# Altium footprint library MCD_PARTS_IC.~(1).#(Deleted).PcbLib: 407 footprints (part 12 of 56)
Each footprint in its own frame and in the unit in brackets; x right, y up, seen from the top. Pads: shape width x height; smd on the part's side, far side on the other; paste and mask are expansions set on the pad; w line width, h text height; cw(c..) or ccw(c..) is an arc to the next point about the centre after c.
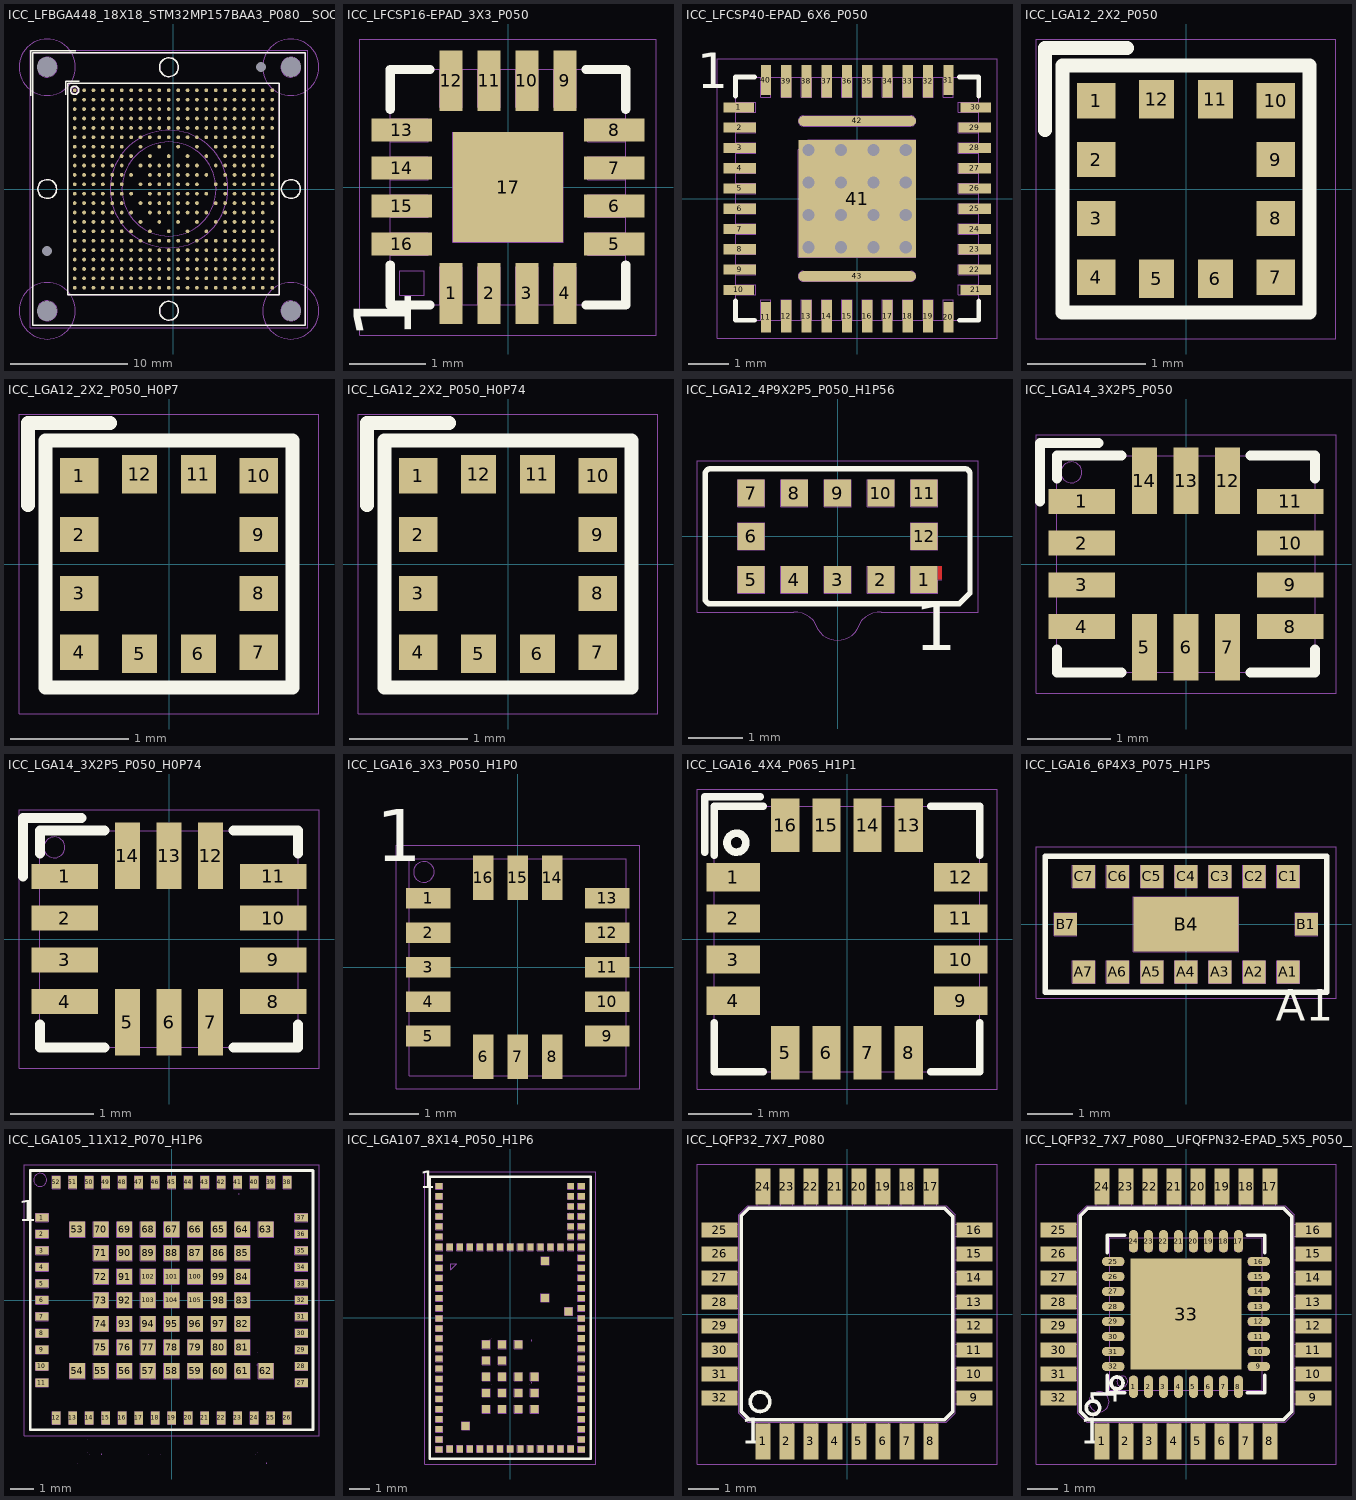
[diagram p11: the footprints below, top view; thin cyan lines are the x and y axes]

## ICC_LFBGA448_18X18_STM32MP157BAA3_P080__SOCKET_IE_CS1627194MF [mm]
height 10.2
pads (454):
  round 0.32 smd mask+0.05: A1(-8.4,8.4) A2(-7.6,8.4) A3(-6.8,8.4) A4(-6,8.4) A5(-5.2,8.4) A6(-4.4,8.4) A7(-3.6,8.4) A8(-2.8,8.4) A9(-2,8.4) A10(-1.2,8.4) A11(-0.4,8.4) A12(0.4,8.4) A13(1.2,8.4) A14(2,8.4) A15(2.8,8.4) A16(3.6,8.4) A17(4.4,8.4) A18(5.2,8.4) A19(6,8.4) A20(6.8,8.4) A21(7.6,8.4) A22(8.4,8.4) AA1(-8.4,-7.6) AA2(-7.6,-7.6) AA3(-6.8,-7.6) AA4(-6,-7.6) AA5(-5.2,-7.6) AA6(-4.4,-7.6) AA7(-3.6,-7.6) AA8(-2.8,-7.6) AA9(-2,-7.6) AA10(-1.2,-7.6) AA11(-0.4,-7.6) AA12(0.4,-7.6) AA13(1.2,-7.6) AA14(2,-7.6) AA15(2.8,-7.6) AA16(3.6,-7.6) AA17(4.4,-7.6) AA18(5.2,-7.6) AA19(6,-7.6) AA20(6.8,-7.6) AA21(7.6,-7.6) AA22(8.4,-7.6) AB1(-8.4,-8.4) AB2(-7.6,-8.4) AB3(-6.8,-8.4) AB4(-6,-8.4) AB5(-5.2,-8.4) AB6(-4.4,-8.4) AB7(-3.6,-8.4) AB8(-2.8,-8.4) AB9(-2,-8.4) AB10(-1.2,-8.4) AB11(-0.4,-8.4) AB12(0.4,-8.4) AB13(1.2,-8.4) AB14(2,-8.4) AB15(2.8,-8.4) AB16(3.6,-8.4) AB17(4.4,-8.4) AB18(5.2,-8.4) AB19(6,-8.4) AB20(6.8,-8.4) AB21(7.6,-8.4) AB22(8.4,-8.4) B1(-8.4,7.6) B2(-7.6,7.6) B3(-6.8,7.6) B4(-6,7.6) B5(-5.2,7.6) B6(-4.4,7.6) B7(-3.6,7.6) B8(-2.8,7.6) B9(-2,7.6) B10(-1.2,7.6) B11(-0.4,7.6) B12(0.4,7.6) B13(1.2,7.6) B14(2,7.6) B15(2.8,7.6) B16(3.6,7.6) B17(4.4,7.6) B18(5.2,7.6) B19(6,7.6) B20(6.8,7.6) B21(7.6,7.6) B22(8.4,7.6) C1(-8.4,6.8) C2(-7.6,6.8) C3(-6.8,6.8) C4(-6,6.8) C5(-5.2,6.8) C6(-4.4,6.8) C7(-3.6,6.8) C8(-2.8,6.8) C9(-2,6.8) C10(-1.2,6.8) C11(-0.4,6.8) C12(0.4,6.8) C13(1.2,6.8) C14(2,6.8) C15(2.8,6.8) C16(3.6,6.8) C17(4.4,6.8) C18(5.2,6.8) C19(6,6.8) C20(6.8,6.8) C21(7.6,6.8) C22(8.4,6.8) D1(-8.4,6) D2(-7.6,6) D3(-6.8,6) D4(-6,6) D5(-5.2,6) D6(-4.4,6) D7(-3.6,6) D8(-2.8,6) D9(-2,6) D10(-1.2,6) D11(-0.4,6) D12(0.4,6) D13(1.2,6) D14(2,6) D15(2.8,6) D16(3.6,6) D17(4.4,6) D18(5.2,6) D19(6,6) D20(6.8,6) D21(7.6,6) D22(8.4,6) E1(-8.4,5.2) E2(-7.6,5.2) E3(-6.8,5.2) E4(-6,5.2) E5(-5.2,5.2) E6(-4.4,5.2) E7(-3.6,5.2) E8(-2.8,5.2) E9(-2,5.2) E10(-1.2,5.2) E11(-0.4,5.2) E12(0.4,5.2) E13(1.2,5.2) E14(2,5.2) E15(2.8,5.2) E16(3.6,5.2) E17(4.4,5.2) E18(5.2,5.2) E19(6,5.2) E20(6.8,5.2) E21(7.6,5.2) E22(8.4,5.2) F1(-8.4,4.4) F2(-7.6,4.4) F3(-6.8,4.4) F4(-6,4.4) F5(-5.2,4.4) F6(-4.4,4.4) F7(-3.6,4.4) F8(-2.8,4.4) F9(-2,4.4) F10(-1.2,4.4) F11(-0.4,4.4) F12(0.4,4.4) F13(1.2,4.4) F14(2,4.4) F15(2.8,4.4) F16(3.6,4.4) F17(4.4,4.4) F18(5.2,4.4) F19(6,4.4) F20(6.8,4.4) F21(7.6,4.4) G1(-8.4,3.6) G2(-7.6,3.6) G3(-6.8,3.6) G4(-6,3.6) G5(-5.2,3.6) G6(-4.4,3.6) G8(-2.8,3.6) G10(-1.2,3.6) G12(0.4,3.6) G14(2,3.6) G16(3.6,3.6) G17(4.4,3.6) G18(5.2,3.6) G19(6,3.6) G20(6.8,3.6) G21(7.6,3.6) G22(8.4,3.6) H1(-8.4,2.8) H2(-7.6,2.8) H3(-6.8,2.8) H4(-6,2.8) H5(-5.2,2.8) H6(-4.4,2.8) H7(-3.6,2.8) H9(-2,2.8) H11(-0.4,2.8) H13(1.2,2.8) H15(2.8,2.8) H17(4.4,2.8) H18(5.2,2.8) H19(6,2.8) H20(6.8,2.8) H21(7.6,2.8) H22(8.4,2.8) J1(-8.4,2) J2(-7.6,2) J3(-6.8,2) J4(-6,2) J5(-5.2,2) J6(-4.4,2) J8(-2.8,2) J9(-2,2) J10(-1.2,2) J11(-0.4,2) J12(0.4,2) J13(1.2,2) J14(2,2) J16(3.6,2) J17(4.4,2) J18(5.2,2) J19(6,2) J20(6.8,2) J21(7.6,2) K1(-8.4,1.2) K2(-7.6,1.2) K3(-6.8,1.2) K4(-6,1.2) K5(-5.2,1.2) K6(-4.4,1.2) K7(-3.6,1.2) K9(-2,1.2) K10(-1.2,1.2) K11(-0.4,1.2) K12(0.4,1.2) K13(1.2,1.2) K14(2,1.2) K15(2.8,1.2) K17(4.4,1.2) K18(5.2,1.2) K19(6,1.2) K20(6.8,1.2) K21(7.6,1.2) K22(8.4,1.2) L1(-8.4,0.4) L2(-7.6,0.4) L3(-6.8,0.4) L4(-6,0.4) L5(-5.2,0.4) L6(-4.4,0.4) L8(-2.8,0.4) L9(-2,0.4) L10(-1.2,0.4) L11(-0.4,0.4) L12(0.4,0.4) L13(1.2,0.4) L14(2,0.4) L16(3.6,0.4) L17(4.4,0.4) L18(5.2,0.4) L19(6,0.4) L20(6.8,0.4) L21(7.6,0.4) L22(8.4,0.4) M1(-8.4,-0.4) M2(-7.6,-0.4) M3(-6.8,-0.4) M4(-6,-0.4) M5(-5.2,-0.4) M6(-4.4,-0.4) M7(-3.6,-0.4) M9(-2,-0.4) M10(-1.2,-0.4) M11(-0.4,-0.4) M12(0.4,-0.4) M13(1.2,-0.4) M14(2,-0.4) M15(2.8,-0.4) M17(4.4,-0.4) M18(5.2,-0.4) M19(6,-0.4) M20(6.8,-0.4) M21(7.6,-0.4) M22(8.4,-0.4) N1(-8.4,-1.2) N2(-7.6,-1.2) N3(-6.8,-1.2) N4(-6,-1.2) N5(-5.2,-1.2) N6(-4.4,-1.2) N8(-2.8,-1.2) N9(-2,-1.2) N10(-1.2,-1.2) N11(-0.4,-1.2) N12(0.4,-1.2) N13(1.2,-1.2) N14(2,-1.2) N16(3.6,-1.2) N17(4.4,-1.2) N18(5.2,-1.2) N19(6,-1.2) N20(6.8,-1.2) N21(7.6,-1.2) N22(8.4,-1.2) P1(-8.4,-2) P2(-7.6,-2) P3(-6.8,-2) P4(-6,-2) P5(-5.2,-2) P6(-4.4,-2) P7(-3.6,-2) P9(-2,-2) P10(-1.2,-2) P11(-0.4,-2) P12(0.4,-2) P13(1.2,-2) P14(2,-2) P15(2.8,-2) P17(4.4,-2) P18(5.2,-2) P19(6,-2) P20(6.8,-2) P21(7.6,-2) R1(-8.4,-2.8) R2(-7.6,-2.8) R3(-6.8,-2.8) R4(-6,-2.8) R5(-5.2,-2.8) R6(-4.4,-2.8) R8(-2.8,-2.8) R10(-1.2,-2.8) R12(0.4,-2.8) R14(2,-2.8) R16(3.6,-2.8) R17(4.4,-2.8) R18(5.2,-2.8) R19(6,-2.8) R20(6.8,-2.8) R21(7.6,-2.8) R22(8.4,-2.8) T1(-8.4,-3.6) T2(-7.6,-3.6) T3(-6.8,-3.6) T4(-6,-3.6) T5(-5.2,-3.6) T6(-4.4,-3.6) T7(-3.6,-3.6) T9(-2,-3.6) T11(-0.4,-3.6) T13(1.2,-3.6) T15(2.8,-3.6) T17(4.4,-3.6) T18(5.2,-3.6) T19(6,-3.6) T20(6.8,-3.6) T21(7.6,-3.6) T22(8.4,-3.6) U1(-8.4,-4.4) U2(-7.6,-4.4) U3(-6.8,-4.4) U4(-6,-4.4) U5(-5.2,-4.4) U6(-4.4,-4.4) U7(-3.6,-4.4) U8(-2.8,-4.4) U9(-2,-4.4) U10(-1.2,-4.4) U11(-0.4,-4.4) U12(0.4,-4.4) U13(1.2,-4.4) U14(2,-4.4) U15(2.8,-4.4) U16(3.6,-4.4) U17(4.4,-4.4) U18(5.2,-4.4) U19(6,-4.4) U20(6.8,-4.4) U21(7.6,-4.4) V1(-8.4,-5.2) V2(-7.6,-5.2) V3(-6.8,-5.2) V4(-6,-5.2) V5(-5.2,-5.2) V6(-4.4,-5.2) V7(-3.6,-5.2) V8(-2.8,-5.2) V9(-2,-5.2) V10(-1.2,-5.2) V11(-0.4,-5.2) V12(0.4,-5.2) V13(1.2,-5.2) V14(2,-5.2) V15(2.8,-5.2) V16(3.6,-5.2) V17(4.4,-5.2) V18(5.2,-5.2) V19(6,-5.2) V20(6.8,-5.2) V21(7.6,-5.2) V22(8.4,-5.2) W1(-8.4,-6) W2(-7.6,-6) W3(-6.8,-6) W4(-6,-6) W5(-5.2,-6) W6(-4.4,-6) W7(-3.6,-6) W8(-2.8,-6) W9(-2,-6) W10(-1.2,-6) W11(-0.4,-6) W12(0.4,-6) W13(1.2,-6) W14(2,-6) W15(2.8,-6) W16(3.6,-6) W17(4.4,-6) W18(5.2,-6) W19(6,-6) W20(6.8,-6) W21(7.6,-6) W22(8.4,-6) Y1(-8.4,-6.8) Y2(-7.6,-6.8) Y3(-6.8,-6.8) Y4(-6,-6.8) Y5(-5.2,-6.8) Y6(-4.4,-6.8) Y7(-3.6,-6.8) Y8(-2.8,-6.8) Y9(-2,-6.8) Y10(-1.2,-6.8) Y11(-0.4,-6.8) Y12(0.4,-6.8) Y13(1.2,-6.8) Y14(2,-6.8) Y15(2.8,-6.8) Y16(3.6,-6.8) Y17(4.4,-6.8) Y18(5.2,-6.8) Y19(6,-6.8) Y20(6.8,-6.8) Y21(7.6,-6.8) Y22(8.4,-6.8)
  round 0.5 hole 1.7 unplated mask+0.05: NPTH1(-10.737,10.362) NPTH2(9.987,10.362) NPTH3(-10.737,-10.362) NPTH4(9.987,-10.362)
  round 0.5 hole 0.85 unplated mask+0.05: NPTH5(-10.737,-5.282) NPTH6(7.447,10.362)
Top Overlay:
  circle w0.12: c-8.4,8.4 r0.35
  circle w0.12: c-0.375,10.362 r0.8
  circle w0.12: c-0.375,-10.362 r0.8
  circle w0.12: c9.987,0 r0.8
  circle w0.12: c-10.737,0 r0.8
  lines w0.12: -12.125,7.95 -12.125,11.75 -8.325,11.75 ; -9.15,8 -9.15,9.15 -8,9.15 ; -11.987,-11.613 -11.987,11.612 11.238,11.612 11.238,-11.613 -11.987,-11.613 ; -9,-9 -9,9 9,9 9,-9 -9,-9
Bottom Overlay:
  circle w0.12: c-10.737,-10.362 r2.4
  circle w0.12: c-10.737,10.362 r2.4
  circle w0.12: c9.987,10.362 r2.4
  circle w0.12: c9.987,-10.362 r2.4
  circle w0.12: c-10.737,-10.362 r1
  circle w0.12: c-10.737,10.362 r1
  circle w0.12: c9.987,10.362 r1
  circle w0.12: c9.987,-10.362 r1
M14-Top Assembly:
  circle w0.01: c-0.375,10.362 r0.8
  circle w0.01: c-0.375,-10.362 r0.8
  circle w0.01: c9.987,0 r0.8
  circle w0.01: c-10.737,0 r0.8
  circle w0.01: c-8.4,8.4 r0.275
  circle w0.01: c-0.375,0 r4
  circle w0.01: c-0.375,0 r5
  lines w0.01: -11.987,-11.613 -11.987,11.612 11.238,11.612 11.238,-11.613 -11.987,-11.613 ; -9,-9 -9,9 9,9 9,-9 -9,-9
  text "'.Designator'" at -2,-0.5 h0.75
  text "A1" at -8.65,8.225 h0.4
M15-Bottom Assembly:
  circle w0.01: c-10.737,-10.362 r2.4
  circle w0.01: c-10.737,10.362 r2.4
  circle w0.01: c9.987,10.362 r2.4
  circle w0.01: c9.987,-10.362 r2.4
  circle w0.01: c-10.737,-10.362 r0.85
  circle w0.01: c-10.737,10.362 r0.85
  circle w0.01: c9.987,10.362 r0.85
  circle w0.01: c9.987,-10.362 r0.85
M16-Top Courtyard:
  lines w0.01: -12.2,-11.825 -12.2,11.825 11.45,11.825 11.45,-11.825 -12.2,-11.825
3D body: height 7, standoff 0, extent -11.987,-11.613 11.238,11.612
3D body: height 9, standoff 7, extent -11.987,-11.613 11.238,11.612
3D body: height -1.6, standoff -5.42, extent 9.144,-11.21 10.837,-9.513
3D body: height -1.6, standoff -5.42, extent -11.58,-11.21 -9.887,-9.514
3D body: height -1.6, standoff -5.42, extent 9.144,9.514 10.837,11.211
3D body: height -1.6, standoff -5.42, extent -11.58,9.514 -9.887,11.21
3D body: height -1.6, standoff -2.87, extent 7.687,-12.662 12.287,-8.062
3D body: height -1.6, standoff -2.87, extent -13.037,-12.662 -8.437,-8.062
3D body: height -1.6, standoff -2.87, extent 7.687,8.062 12.287,12.662
3D body: height -1.6, standoff -2.87, extent -13.037,8.062 -8.437,12.662
3D body: height -1.6, standoff -2.23, extent 7.587,-12.762 12.387,-7.962
3D body: height -1.6, standoff -2.23, extent 7.587,7.962 12.387,12.762
3D body: height -1.6, standoff -2.23, extent -13.137,7.962 -8.337,12.762
3D body: height -1.6, standoff -2.23, extent -13.137,-12.762 -8.337,-7.962
3D body: height 9.87, standoff 9, extent -5.375,-5 4.625,5
3D body: height 9.87, standoff 9, extent -4.375,-3.997 3.625,3.997
3D body: height 10.18, standoff 9, extent -11.531,-0.798 -9.937,0.799
3D body: height 10.18, standoff 9, extent -1.169,9.564 0.425,11.161
3D body: height 10.18, standoff 9, extent 9.193,-0.798 10.787,0.799
3D body: height 10.18, standoff 9, extent -1.169,-11.16 0.425,-9.563

## ICC_LFCSP16-EPAD_3X3_P050 [mm] "MCD-02980"
height 0.8
pads (17):
  rect 0.3x0.8 smd mask+0.05: 1(-0.75,-1.4) 2(-0.25,-1.4) 3(0.25,-1.4) 4(0.75,-1.4) 9(0.75,1.4) 10(0.25,1.4) 11(-0.25,1.4) 12(-0.75,1.4)
  rect 0.8x0.3 smd mask+0.05: 5(1.4,-0.75) 6(1.4,-0.25) 7(1.4,0.25) 8(1.4,0.75) 13(-1.4,0.75) 14(-1.4,0.25) 15(-1.4,-0.25) 16(-1.4,-0.75)
  rect 1.45x1.45 smd mask+0.05: 17(0,0)
Top Overlay:
  lines w0.12: -1.55,-1.025 -1.55,-1.55 -1.025,-1.55 ; -1.55,1.025 -1.55,1.55 -1.025,1.55 ; 1.025,-1.55 1.55,-1.55 1.55,-1.025 ; 1.025,1.55 1.55,1.55 1.55,1.025
  text "1" at -1.025,-2 h1.3
M14-Top Assembly:
  lines w0.01: -1.55,-0.9 -1.05,-0.9 -1.05,-0.6 -1.55,-0.6 ; -1.55,-0.4 -1.05,-0.4 -1.05,-0.1 -1.55,-0.1 ; -1.55,0.1 -1.05,0.1 -1.05,0.4 -1.55,0.4 ; -1.55,0.6 -1.05,0.6 -1.05,0.9 -1.55,0.9 ; -0.9,-1.55 -0.9,-1.05 -0.6,-1.05 -0.6,-1.55 ; -0.9,1.55 -0.9,1.05 -0.6,1.05 -0.6,1.55 ; -0.4,-1.55 -0.4,-1.05 -0.1,-1.05 -0.1,-1.55 ; -0.4,1.55 -0.4,1.05 -0.1,1.05 -0.1,1.55 ; 0.1,-1.55 0.1,-1.05 0.4,-1.05 0.4,-1.55 ; 0.1,1.55 0.1,1.05 0.4,1.05 0.4,1.55 ; 0.6,-1.55 0.6,-1.05 0.9,-1.05 0.9,-1.55 ; 0.6,1.55 0.6,1.05 0.9,1.05 0.9,1.55 ; 1.55,-0.9 1.05,-0.9 1.05,-0.6 1.55,-0.6 ; 1.55,-0.4 1.05,-0.4 1.05,-0.1 1.55,-0.1 ; 1.55,0.1 1.05,0.1 1.05,0.4 1.55,0.4 ; 1.55,0.6 1.05,0.6 1.05,0.9 1.55,0.9 ; -1.55,-1.55 1.55,-1.55 1.55,1.55 -1.55,1.55 -1.55,-1.55 ; -1.425,-1.425 -1.1,-1.425 -1.1,-1.1 -1.425,-1.1 -1.425,-1.425 ; -0.725,-0.725 0.725,-0.725 0.725,0.725 -0.725,0.725 -0.725,-0.725
  text "16" at -1.4,-0.575 h0.4
  text "13" at -1.4,0.925 h0.4
  text "12" at -0.575,1.4 h0.4
  text "9" at 0.805,1.399 h0.4
  text "8" at 1.399,0.66 h0.4
  text "5" at 1.399,-0.805 h0.4
  text "'.Designator'" at -2,-0.5 h0.75
  text "17" at -0.15,-0.125 h0.4
  text "4" at 0.66,-1.399 h0.4
  text "1" at -0.805,-1.399 h0.4
M16-Top Courtyard:
  lines w0.01: -1.95,-1.95 -1.95,1.95 1.95,1.95 1.95,-1.95 -1.95,-1.95
3D body: height 0.8, standoff 0, extent -1.55,-1.55 1.55,1.55

## ICC_LFCSP40-EPAD_6X6_P050 [mm] "MCD-02639"
height 0.8
pads (43):
  rect 0.75x0.25 smd mask+0.05: 1(-2.925,2.25) 10(-2.925,-2.25) 21(2.925,-2.25) 30(2.925,2.25)
  rect 0.8x0.25 smd mask+0.05: 2(-2.9,1.75) 3(-2.9,1.25) 4(-2.9,0.75) 5(-2.9,0.25) 6(-2.9,-0.25) 7(-2.9,-0.75) 8(-2.9,-1.25) 9(-2.9,-1.75) 22(2.9,-1.75) 23(2.9,-1.25) 24(2.9,-0.75) 25(2.9,-0.25) 26(2.9,0.25) 27(2.9,0.75) 28(2.9,1.25) 29(2.9,1.75)
  rect 0.25x0.75 smd mask+0.05: 11(-2.25,-2.925) 20(2.25,-2.925) 31(2.25,2.925) 40(-2.25,2.925)
  rect 0.25x0.8 smd mask+0.05: 12(-1.75,-2.9) 13(-1.25,-2.9) 14(-0.75,-2.9) 15(-0.25,-2.9) 16(0.25,-2.9) 17(0.75,-2.9) 18(1.25,-2.9) 19(1.75,-2.9) 32(1.75,2.9) 33(1.25,2.9) 34(0.75,2.9) 35(0.25,2.9) 36(-0.25,2.9) 37(-0.75,2.9) 38(-1.25,2.9) 39(-1.75,2.9)
  rect 2.9x2.9 smd mask+0.05: 41(0,0)
  rrect100% 2.9x0.25 smd mask+0.05: 42(0,1.915) 43(0,-1.915)
via 1.2,-1.2 diameter 0.5 hole 0.3
via 0.4,-1.2 diameter 0.5 hole 0.3
via 0.4,-0.4 diameter 0.5 hole 0.3
via 1.2,-0.4 diameter 0.5 hole 0.3
via 1.2,0.4 diameter 0.5 hole 0.3
via 0.4,0.4 diameter 0.5 hole 0.3
via 1.2,1.2 diameter 0.5 hole 0.3
via 0.4,1.2 diameter 0.5 hole 0.3
via -0.4,1.2 diameter 0.5 hole 0.3
via -0.4,0.4 diameter 0.5 hole 0.3
via -0.4,-0.4 diameter 0.5 hole 0.3
via -0.4,-1.2 diameter 0.5 hole 0.3
via -1.2,-1.2 diameter 0.5 hole 0.3
via -1.2,-0.4 diameter 0.5 hole 0.3
via -1.2,0.4 diameter 0.5 hole 0.3
via -1.2,1.2 diameter 0.5 hole 0.3
Top Overlay:
  lines w0.12: -3,-2.525 -3,-3 -2.525,-3 ; -3,2.525 -3,3 -2.525,3 ; 2.525,-3 3,-3 3,-2.525 ; 2.525,3 3,3 3,2.525
  text "1" at -3.95,2.425 h1.5
M14-Top Assembly:
  lines w0.01: -3,-2.375 -2.5,-2.375 -2.5,-2.125 -3,-2.125 ; -3,-1.875 -2.5,-1.875 -2.5,-1.625 -3,-1.625 ; -3,-1.375 -2.5,-1.375 -2.5,-1.125 -3,-1.125 ; -3,-0.875 -2.5,-0.875 -2.5,-0.625 -3,-0.625 ; -3,-0.375 -2.5,-0.375 -2.5,-0.125 -3,-0.125 ; -3,0.125 -2.5,0.125 -2.5,0.375 -3,0.375 ; -3,0.625 -2.5,0.625 -2.5,0.875 -3,0.875 ; -3,1.125 -2.5,1.125 -2.5,1.375 -3,1.375 ; -3,1.625 -2.5,1.625 -2.5,1.875 -3,1.875 ; -3,2.125 -2.5,2.125 -2.5,2.375 -3,2.375 ; -2.375,-3 -2.375,-2.5 -2.125,-2.5 -2.125,-3 ; -2.375,3 -2.375,2.5 -2.125,2.5 -2.125,3 ; -1.875,-3 -1.875,-2.5 -1.625,-2.5 -1.625,-3 ; -1.875,3 -1.875,2.5 -1.625,2.5 -1.625,3 ; -1.375,-3 -1.375,-2.5 -1.125,-2.5 -1.125,-3 ; -1.375,3 -1.375,2.5 -1.125,2.5 -1.125,3 ; -0.875,-3 -0.875,-2.5 -0.625,-2.5 -0.625,-3 ; -0.875,3 -0.875,2.5 -0.625,2.5 -0.625,3 ; -0.375,-3 -0.375,-2.5 -0.125,-2.5 -0.125,-3 ; -0.375,3 -0.375,2.5 -0.125,2.5 -0.125,3 ; 0.125,-3 0.125,-2.5 0.375,-2.5 0.375,-3 ; 0.125,3 0.125,2.5 0.375,2.5 0.375,3 ; 0.625,-3 0.625,-2.5 0.875,-2.5 0.875,-3 ; 0.625,3 0.625,2.5 0.875,2.5 0.875,3 ; 1.125,-3 1.125,-2.5 1.375,-2.5 1.375,-3 ; 1.125,3 1.125,2.5 1.375,2.5 1.375,3 ; 1.625,-3 1.625,-2.5 1.875,-2.5 1.875,-3 ; 1.625,3 1.625,2.5 1.875,2.5 1.875,3 ; 2.125,-3 2.125,-2.5 2.375,-2.5 2.375,-3 ; 2.125,3 2.125,2.5 2.375,2.5 2.375,3 ; 3,-2.375 2.5,-2.375 2.5,-2.125 3,-2.125 ; 3,-1.875 2.5,-1.875 2.5,-1.625 3,-1.625 ; 3,-1.375 2.5,-1.375 2.5,-1.125 3,-1.125 ; 3,-0.875 2.5,-0.875 2.5,-0.625 3,-0.625 ; 3,-0.375 2.5,-0.375 2.5,-0.125 3,-0.125 ; 3,0.125 2.5,0.125 2.5,0.375 3,0.375 ; 3,0.625 2.5,0.625 2.5,0.875 3,0.875 ; 3,1.125 2.5,1.125 2.5,1.375 3,1.375 ; 3,1.625 2.5,1.625 2.5,1.875 3,1.875 ; 3,2.125 2.5,2.125 2.5,2.375 3,2.375 ; -3,-3 3,-3 3,3 -3,3 -3,-3 ; -1.45,-1.915 ccw(c-1.325,-1.915) -1.325,-2.04 1.325,-2.04 ccw(c1.325,-1.915) 1.45,-1.915 ccw(c1.325,-1.915) 1.325,-1.79 -1.325,-1.79 ccw(c-1.325,-1.915) -1.45,-1.915 ; -1.45,-1.45 1.45,-1.45 1.45,1.45 -1.2,1.45 -1.45,1.2 -1.45,-1.45 ; -1.45,1.915 cw(c-1.325,1.915) -1.325,2.04 1.325,2.04 cw(c1.325,1.915) 1.45,1.915 cw(c1.325,1.915) 1.325,1.79 -1.325,1.79 cw(c-1.325,1.915) -1.45,1.915
  text "40" at -2.475,2.575 h0.5
  text "31" at 2.075,2.6 h0.5
  text "30" at 2.5,2.1 h0.5
  text "21" at 2.5,-2.4 h0.5
  text "20" at 2,-2.9 h0.5
  text "11" at -2.475,-2.9 h0.5
  text "10" at -2.95,-2.4 h0.5
  text "1" at -2.85,2.1 h0.5
  text "'.Designator'" at 0,0 h0.75
M16-Top Courtyard:
  lines w0.01: -3.45,-3.45 3.45,-3.45 3.45,3.45 -1.45,3.45 -3.45,3.45 -3.45,-3.45
3D body: height 0.82, standoff 0.81, extent -2.848,2.351 -2.35,2.85
3D body: height 0.61, standoff 0.6, extent -2.848,2.351 -2.35,2.85
3D body: height 0.8, standoff 0, extent -3,-3 3,3

## ICC_LGA12_2X2_P050 [mm] "MCD-00709"
height 1
pads (12):
  rect 0.325x0.3 smd mask+0.05: 1(-0.763,0.75) 2(-0.763,0.25) 3(-0.763,-0.25) 4(-0.763,-0.75) 7(0.763,-0.75) 8(0.763,-0.25) 9(0.763,0.25) 10(0.763,0.75)
  rect 0.3x0.325 smd mask+0.05: 5(-0.25,-0.762) 6(0.25,-0.762) 11(0.25,0.763) 12(-0.25,0.763)
Top Overlay:
  lines w0.12: -1.2,0.5 -1.2,1.2 -0.5,1.2 ; -1.05,-1.05 -1.05,1.05 1.05,1.05 1.05,-1.05 -1.05,-1.05
M14-Top Assembly:
  lines w0.01: -1.05,-1.05 1.05,-1.05 1.05,1.05 -1.05,1.05 -1.05,-1.05 ; -0.9,-0.875 -0.625,-0.875 -0.625,-0.625 -0.9,-0.625 -0.9,-0.875 ; -0.9,-0.375 -0.625,-0.375 -0.625,-0.125 -0.9,-0.125 -0.9,-0.375 ; -0.9,0.125 -0.625,0.125 -0.625,0.375 -0.9,0.375 -0.9,0.125 ; -0.9,0.625 -0.75,0.625 -0.625,0.75 -0.625,0.875 -0.9,0.875 -0.9,0.625 ; -0.375,-0.9 -0.125,-0.9 -0.125,-0.625 -0.375,-0.625 -0.375,-0.9 ; -0.375,0.625 -0.375,0.9 -0.125,0.9 -0.125,0.625 -0.375,0.625 ; 0.125,-0.9 0.375,-0.9 0.375,-0.625 0.125,-0.625 0.125,-0.9 ; 0.125,0.625 0.375,0.625 0.375,0.9 0.125,0.9 0.125,0.625 ; 0.625,-0.875 0.9,-0.875 0.9,-0.625 0.625,-0.625 0.625,-0.875 ; 0.625,-0.375 0.9,-0.375 0.9,-0.125 0.625,-0.125 0.625,-0.375 ; 0.625,0.125 0.9,0.125 0.9,0.375 0.625,0.375 0.625,0.125 ; 0.625,0.625 0.9,0.625 0.9,0.875 0.625,0.875 0.625,0.625
  text "'.Designator'" at -2,-0.5 h0.75
  text "1" at -0.825,0.65 h0.3
  text "2" at -0.825,0.15 h0.3
  text "3" at -0.825,-0.35 h0.3
  text "4" at -0.825,-0.85 h0.3
  text "5" at -0.325,-0.85 h0.3
  text "6" at 0.175,-0.85 h0.3
  text "7" at 0.7,-0.85 h0.3
  text "8" at 0.7,-0.35 h0.3
  text "9" at 0.7,0.15 h0.3
  text "10" at 0.637,0.65 h0.3
  text "12" at -0.375,0.663 h0.3
  text "11" at 0.138,0.663 h0.3
M16-Top Courtyard:
  lines w0.01: -1.275,-1.275 1.275,-1.275 1.275,1.275 -1.275,1.275 -1.275,-1.275
3D body: height 1.01, standoff 1, extent -0.998,0.501 -0.5,1
3D body: height 1, standoff 0, extent -1.05,-1.05 1.05,1.05
3D body "LGA12-2x2x0_9.STEP": height 0.95, standoff 0, extent -1,-1 1,1

## ICC_LGA12_2X2_P050_H0P7 [mm] "MCD-01448"
height 0.7
pads (12):
  rect 0.325x0.3 smd mask+0.05: 1(-0.763,0.75) 2(-0.763,0.25) 3(-0.763,-0.25) 4(-0.763,-0.75) 7(0.763,-0.75) 8(0.763,-0.25) 9(0.763,0.25) 10(0.763,0.75)
  rect 0.3x0.325 smd mask+0.05: 5(-0.25,-0.762) 6(0.25,-0.762) 11(0.25,0.763) 12(-0.25,0.763)
Top Overlay:
  lines w0.12: -1.2,0.5 -1.2,1.2 -0.5,1.2 ; -1.05,-1.05 1.05,-1.05 1.05,1.05 -1.05,1.05 -1.05,-1.05
M14-Top Assembly:
  lines w0.01: -1.05,-1.05 -1.05,1.05 1.05,1.05 1.05,-1.05 -1.05,-1.05 ; -0.9,-0.875 -0.9,-0.625 -0.625,-0.625 -0.625,-0.875 -0.9,-0.875 ; -0.9,-0.375 -0.9,-0.125 -0.625,-0.125 -0.625,-0.375 -0.9,-0.375 ; -0.9,0.125 -0.9,0.375 -0.625,0.375 -0.625,0.125 -0.9,0.125 ; -0.9,0.625 -0.9,0.875 -0.625,0.875 -0.625,0.75 -0.75,0.625 -0.9,0.625 ; -0.375,-0.9 -0.375,-0.625 -0.125,-0.625 -0.125,-0.9 -0.375,-0.9 ; -0.375,0.625 -0.125,0.625 -0.125,0.9 -0.375,0.9 -0.375,0.625 ; 0.125,-0.9 0.125,-0.625 0.375,-0.625 0.375,-0.9 0.125,-0.9 ; 0.125,0.625 0.125,0.9 0.375,0.9 0.375,0.625 0.125,0.625 ; 0.625,-0.875 0.625,-0.625 0.9,-0.625 0.9,-0.875 0.625,-0.875 ; 0.625,-0.375 0.625,-0.125 0.9,-0.125 0.9,-0.375 0.625,-0.375 ; 0.625,0.125 0.625,0.375 0.9,0.375 0.9,0.125 0.625,0.125 ; 0.625,0.625 0.625,0.875 0.9,0.875 0.9,0.625 0.625,0.625
  text "11" at 0.138,0.663 h0.3
  text "12" at -0.375,0.663 h0.3
  text "10" at 0.637,0.65 h0.3
  text "9" at 0.7,0.15 h0.3
  text "8" at 0.7,-0.35 h0.3
  text "7" at 0.7,-0.85 h0.3
  text "6" at 0.175,-0.85 h0.3
  text "5" at -0.325,-0.85 h0.3
  text "4" at -0.825,-0.85 h0.3
  text "3" at -0.825,-0.35 h0.3
  text "2" at -0.825,0.15 h0.3
  text "1" at -0.825,0.65 h0.3
  text "'.Designator'" at -2,-0.5 h0.75
M16-Top Courtyard:
  lines w0.01: -1.275,-1.275 -1.275,1.275 1.275,1.275 1.275,-1.275 -1.275,-1.275
3D body: height 0.7, standoff 0, extent -1.05,-1.05 1.05,1.05
3D body: height 0.71, standoff 0.7, extent -0.998,0.501 -0.5,1

## ICC_LGA12_2X2_P050_H0P74 [mm]
height 0.74
pads (12):
  rect 0.325x0.3 smd mask+0.05: 1(-0.763,0.75) 2(-0.763,0.25) 3(-0.763,-0.25) 4(-0.763,-0.75) 7(0.763,-0.75) 8(0.763,-0.25) 9(0.763,0.25) 10(0.763,0.75)
  rect 0.3x0.325 smd mask+0.05: 5(-0.25,-0.762) 6(0.25,-0.762) 11(0.25,0.763) 12(-0.25,0.763)
Top Overlay:
  lines w0.12: -1.2,0.5 -1.2,1.2 -0.5,1.2 ; -1.05,-1.05 -1.05,1.05 1.05,1.05 1.05,-1.05 -1.05,-1.05
M14-Top Assembly:
  lines w0.01: -1.05,-1.05 1.05,-1.05 1.05,1.05 -1.05,1.05 -1.05,-1.05 ; -0.9,-0.875 -0.625,-0.875 -0.625,-0.625 -0.9,-0.625 -0.9,-0.875 ; -0.9,-0.375 -0.625,-0.375 -0.625,-0.125 -0.9,-0.125 -0.9,-0.375 ; -0.9,0.125 -0.625,0.125 -0.625,0.375 -0.9,0.375 -0.9,0.125 ; -0.9,0.625 -0.75,0.625 -0.625,0.75 -0.625,0.875 -0.9,0.875 -0.9,0.625 ; -0.375,-0.9 -0.125,-0.9 -0.125,-0.625 -0.375,-0.625 -0.375,-0.9 ; -0.375,0.625 -0.375,0.9 -0.125,0.9 -0.125,0.625 -0.375,0.625 ; 0.125,-0.9 0.375,-0.9 0.375,-0.625 0.125,-0.625 0.125,-0.9 ; 0.125,0.625 0.375,0.625 0.375,0.9 0.125,0.9 0.125,0.625 ; 0.625,-0.875 0.9,-0.875 0.9,-0.625 0.625,-0.625 0.625,-0.875 ; 0.625,-0.375 0.9,-0.375 0.9,-0.125 0.625,-0.125 0.625,-0.375 ; 0.625,0.125 0.9,0.125 0.9,0.375 0.625,0.375 0.625,0.125 ; 0.625,0.625 0.9,0.625 0.9,0.875 0.625,0.875 0.625,0.625
  text "'.Designator'" at -2,-0.5 h0.75
  text "1" at -0.825,0.65 h0.3
  text "2" at -0.825,0.15 h0.3
  text "3" at -0.825,-0.35 h0.3
  text "4" at -0.825,-0.85 h0.3
  text "5" at -0.325,-0.85 h0.3
  text "6" at 0.175,-0.85 h0.3
  text "7" at 0.7,-0.85 h0.3
  text "8" at 0.7,-0.35 h0.3
  text "9" at 0.7,0.15 h0.3
  text "10" at 0.637,0.65 h0.3
  text "12" at -0.375,0.663 h0.3
  text "11" at 0.138,0.663 h0.3
M16-Top Courtyard:
  lines w0.01: -1.275,-1.275 1.275,-1.275 1.275,1.275 -1.275,1.275 -1.275,-1.275
3D body: height 0.75, standoff 0.74, extent -0.95,0.55 -0.55,0.95
3D body: height 0.74, standoff 0, extent -1.05,-1.05 1.05,1.05

## ICC_LGA12_4P9X2P5_P050_H1P56 [mm] "MCD-02083"
height 1.56
pads (12):
  rect 0.5x0.5 smd mask+0.05: 1(1.6,-0.8) 2(0.8,-0.8) 3(0,-0.8) 4(-0.8,-0.8) 5(-1.6,-0.8) 6(-1.6,0) 7(-1.6,0.8) 8(-0.8,0.8) 9(0,0.8) 10(0.8,0.8) 11(1.6,0.8) 12(1.6,0)
Top Layer:
  rectangle: 1.85,-0.8 1.93,-0.55
Top Overlay:
  lines w0.1: -2.45,-1.15 ccw(c-2.35,-1.15) -2.35,-1.25 2.25,-1.25 2.45,-1.05 2.45,1.15 ccw(c2.35,1.15) 2.35,1.25 -2.35,1.25 ccw(c-2.35,1.15) -2.45,1.15 -2.45,-1.15
  text "1" at 1.425,-2.4 h1.52
M14-Top Assembly:
  lines w0.01: -2.45,-1.15 ccw(c-2.35,-1.15) -2.35,-1.25 2.25,-1.25 2.45,-1.05 2.45,1.15 ccw(c2.35,1.15) 2.35,1.25 -2.35,1.25 ccw(c-2.35,1.15) -2.45,1.15 -2.45,-1.15 ; -1.85,-1.05 -1.85,-0.55 -1.35,-0.55 -1.35,-1.05 -1.85,-1.05 ; -1.85,-0.25 -1.85,0.25 -1.35,0.25 -1.35,-0.25 -1.85,-0.25 ; -1.85,0.55 -1.85,1.05 -1.35,1.05 -1.35,0.55 -1.85,0.55 ; -1.05,-1.05 -1.05,-0.55 -0.55,-0.55 -0.55,-1.05 -1.05,-1.05 ; -1.05,0.55 -1.05,1.05 -0.55,1.05 -0.55,0.55 -1.05,0.55 ; -0.25,-1.05 -0.25,-0.55 0.25,-0.55 0.25,-1.05 -0.25,-1.05 ; -0.25,0.55 -0.25,1.05 0.25,1.05 0.25,0.55 -0.25,0.55 ; 0.55,-1.05 1.05,-1.05 1.05,-0.55 0.55,-0.55 0.55,-1.05 ; 0.55,0.55 0.55,1.05 1.05,1.05 1.05,0.55 0.55,0.55 ; 1.35,-1.05 1.35,-0.55 1.93,-0.55 1.93,-0.8 1.85,-0.8 1.85,-1.05 1.35,-1.05 ; 1.35,-0.25 1.35,0.25 1.85,0.25 1.85,-0.25 1.35,-0.25 ; 1.35,0.55 1.35,1.05 1.85,1.05 1.85,0.55 1.35,0.55
  text "'.Designator'" at -2,-0.5 h0.75
  text "1" at 1.525,-0.95 h0.5
  text "2" at 0.7,-0.95 h0.5
  text "3" at -0.1,-0.95 h0.5
  text "4" at -0.925,-0.95 h0.5
  text "5" at -1.7,-0.95 h0.5
  text "6" at -1.7,-0.15 h0.5
  text "7" at -1.7,0.65 h0.5
  text "8" at -0.9,0.65 h0.5
  text "9" at -0.1,0.65 h0.5
  text "10" at 0.575,0.65 h0.5
  text "11" at 1.4,0.65 h0.5
  text "12" at 1.4,-0.15 h0.5
M16-Top Courtyard:
  lines w0.01: -2.6,-1.4 -0.812,-1.4 cw(c-0.812,-1.912) -0.45,-1.55 -0.4,-1.654 ccw(c0,-1.485) 0,-1.92 ccw(c0,-1.485) 0.4,-1.654 0.45,-1.55 cw(c0.812,-1.912) 0.812,-1.4 2.6,-1.4 2.6,1.4 -2.6,1.4 -2.6,-1.4
3D body: height 1.56, standoff 0, extent -2.45,-1.25 2.45,1.25
3D body "User Library-vl53l1x.STEP": height 1.58, standoff -0.01, extent -2.45,-1.25 2.45,1.25

## ICC_LGA14_3X2P5_P050 [mm] "MCD-01387"
height 0.86
pads (14):
  rect 0.8x0.3 smd mask+0.05: 1(-1.25,0.75) 2(-1.25,0.25) 3(-1.25,-0.25) 4(-1.25,-0.75) 8(1.25,-0.75) 9(1.25,-0.25) 10(1.25,0.25) 11(1.25,0.75)
  rect 0.3x0.8 smd mask+0.05: 5(-0.5,-1) 6(0,-1) 7(0.5,-1) 12(0.5,1) 13(0,1) 14(-0.5,1)
Top Overlay:
  lines w0.12: -1.75,0.75 -1.75,1.45 -1.05,1.45 ; -1.55,-1.025 -1.55,-1.3 -0.775,-1.3 ; -1.55,1.025 -1.55,1.3 -0.775,1.3 ; 0.775,-1.3 1.55,-1.3 1.55,-1.025 ; 0.775,1.3 1.55,1.3 1.55,1.025
M14-Top Assembly:
  circle w0.01: c-1.375,1.1 r0.125
  lines w0.01: -1.55,-1.3 -1.55,1.3 1.55,1.3 1.55,-1.3 -1.55,-1.3 ; -1.45,-0.875 -1.45,-0.625 -0.975,-0.625 -0.975,-0.875 -1.45,-0.875 ; -1.45,-0.375 -1.45,-0.125 -0.975,-0.125 -0.975,-0.375 -1.45,-0.375 ; -1.45,0.125 -1.45,0.375 -0.975,0.375 -0.975,0.125 -1.45,0.125 ; -1.45,0.625 -1.45,0.875 -0.975,0.875 -0.975,0.625 -1.45,0.625 ; -0.625,-1.2 -0.375,-1.2 -0.375,-0.725 -0.625,-0.725 -0.625,-1.2 ; -0.625,0.725 -0.625,1.2 -0.375,1.2 -0.375,0.725 -0.625,0.725 ; -0.125,-1.2 0.125,-1.2 0.125,-0.725 -0.125,-0.725 -0.125,-1.2 ; -0.125,0.725 -0.125,1.2 0.125,1.2 0.125,0.725 -0.125,0.725 ; 0.375,-1.2 0.625,-1.2 0.625,-0.725 0.375,-0.725 0.375,-1.2 ; 0.375,0.725 0.375,1.2 0.625,1.2 0.625,0.725 0.375,0.725 ; 0.975,-0.875 0.975,-0.625 1.45,-0.625 1.45,-0.875 0.975,-0.875 ; 0.975,-0.375 0.975,-0.125 1.45,-0.125 1.45,-0.375 0.975,-0.375 ; 0.975,0.125 0.975,0.375 1.45,0.375 1.45,0.125 0.975,0.125 ; 0.975,0.625 0.975,0.875 1.45,0.875 1.45,0.625 0.975,0.625
  text "14" at -0.7,0.8 h0.5
  text "12" at 0.275,0.8 h0.5
  text "8" at 1.375,-0.85 h0.5
  text "11" at 1.375,0.575 h0.5
  text "5" at -0.6,-1.125 h0.5
  text "7" at 0.4,-1.125 h0.5
  text "4" at -1.375,-0.64 h0.5
  text "1" at -1.375,0.825 h0.5
  text "'.Designator'" at -2,-0.5 h0.75
M16-Top Courtyard:
  lines w0.01: -1.8,-1.55 -1.8,1.55 -0.625,1.55 1.8,1.55 1.8,-1.55 -1.8,-1.55
3D body "LGA-14 2_5x3-1.STEP": height 0.86, standoff 0, extent -1.5,-1.25 1.5,1.25
3D body: height 0.86, standoff 0, extent -1.55,-1.3 1.55,1.3

## ICC_LGA14_3X2P5_P050_H0P74 [mm] "MCD-04163"
height 0.74
pads (14):
  rect 0.8x0.3 smd mask+0.05: 1(-1.25,0.75) 2(-1.25,0.25) 3(-1.25,-0.25) 4(-1.25,-0.75) 8(1.25,-0.75) 9(1.25,-0.25) 10(1.25,0.25) 11(1.25,0.75)
  rect 0.3x0.8 smd mask+0.05: 5(-0.5,-1) 6(0,-1) 7(0.5,-1) 12(0.5,1) 13(0,1) 14(-0.5,1)
Top Overlay:
  lines w0.12: -1.75,0.75 -1.75,1.45 -1.05,1.45 ; -1.55,-1.025 -1.55,-1.3 -0.775,-1.3 ; -1.55,1.025 -1.55,1.3 -0.775,1.3 ; 0.775,-1.3 1.55,-1.3 1.55,-1.025 ; 0.775,1.3 1.55,1.3 1.55,1.025
M14-Top Assembly:
  circle w0.01: c-1.375,1.1 r0.125
  lines w0.01: -1.55,-1.3 -1.55,1.3 1.55,1.3 1.55,-1.3 -1.55,-1.3 ; -1.45,-0.875 -1.45,-0.625 -0.975,-0.625 -0.975,-0.875 -1.45,-0.875 ; -1.45,-0.375 -1.45,-0.125 -0.975,-0.125 -0.975,-0.375 -1.45,-0.375 ; -1.45,0.125 -1.45,0.375 -0.975,0.375 -0.975,0.125 -1.45,0.125 ; -1.45,0.625 -1.45,0.875 -0.975,0.875 -0.975,0.625 -1.45,0.625 ; -0.625,-1.2 -0.375,-1.2 -0.375,-0.725 -0.625,-0.725 -0.625,-1.2 ; -0.625,0.725 -0.625,1.2 -0.375,1.2 -0.375,0.725 -0.625,0.725 ; -0.125,-1.2 0.125,-1.2 0.125,-0.725 -0.125,-0.725 -0.125,-1.2 ; -0.125,0.725 -0.125,1.2 0.125,1.2 0.125,0.725 -0.125,0.725 ; 0.375,-1.2 0.625,-1.2 0.625,-0.725 0.375,-0.725 0.375,-1.2 ; 0.375,0.725 0.375,1.2 0.625,1.2 0.625,0.725 0.375,0.725 ; 0.975,-0.875 0.975,-0.625 1.45,-0.625 1.45,-0.875 0.975,-0.875 ; 0.975,-0.375 0.975,-0.125 1.45,-0.125 1.45,-0.375 0.975,-0.375 ; 0.975,0.125 0.975,0.375 1.45,0.375 1.45,0.125 0.975,0.125 ; 0.975,0.625 0.975,0.875 1.45,0.875 1.45,0.625 0.975,0.625
  text "14" at -0.7,0.8 h0.5
  text "12" at 0.275,0.8 h0.5
  text "8" at 1.375,-0.85 h0.5
  text "11" at 1.375,0.575 h0.5
  text "5" at -0.6,-1.125 h0.5
  text "7" at 0.4,-1.125 h0.5
  text "4" at -1.375,-0.64 h0.5
  text "1" at -1.375,0.825 h0.5
  text "'.Designator'" at 0,0 h0.75
M16-Top Courtyard:
  lines w0.01: -1.8,-1.55 -1.8,1.55 -0.625,1.55 1.8,1.55 1.8,-1.55 -1.8,-1.55
3D body: height 0.74, standoff 0, extent -1.55,-1.3 1.55,1.3
3D body: height 0.75, standoff 0.74, extent -1.45,0.9 -1.15,1.2

## ICC_LGA16_3X3_P050_H1P0 [mm] "MCD-02430"
height 1
pads (16):
  rect 0.65x0.3 smd mask+0.05: 1(-1.3,1) 2(-1.3,0.5) 3(-1.3,0) 4(-1.3,-0.5) 5(-1.3,-1) 9(1.3,-1) 10(1.3,-0.5) 11(1.3,0) 12(1.3,0.5) 13(1.3,1)
  rect 0.3x0.65 smd mask+0.05: 6(-0.5,-1.3) 7(0,-1.3) 8(0.5,-1.3) 14(0.5,1.3) 15(0,1.3) 16(-0.5,1.3)
Top Overlay:
  text "1" at -2.055,1.29 h1.3
M14-Top Assembly:
  circle w0.01: c-1.365,1.385 r0.15
  lines w0.01: -1.575,-1.575 1.575,-1.575 1.575,1.575 -1.575,1.575 -1.575,-1.575 ; -1.4,-1.125 -1.4,-0.875 -1.05,-0.875 -1.05,-1.125 -1.4,-1.125 ; -1.4,-0.625 -1.4,-0.375 -1.05,-0.375 -1.05,-0.625 -1.4,-0.625 ; -1.4,-0.125 -1.4,0.125 -1.05,0.125 -1.05,-0.125 -1.4,-0.125 ; -1.4,0.375 -1.4,0.625 -1.05,0.625 -1.05,0.375 -1.4,0.375 ; -1.4,0.875 -1.4,1.125 -1.05,1.125 -1.05,0.875 -1.4,0.875 ; -0.625,-1.4 -0.625,-1.05 -0.375,-1.05 -0.375,-1.4 -0.625,-1.4 ; -0.625,1.05 -0.375,1.05 -0.375,1.4 -0.625,1.4 -0.625,1.05 ; -0.125,-1.4 -0.125,-1.05 0.125,-1.05 0.125,-1.4 -0.125,-1.4 ; -0.125,1.05 0.125,1.05 0.125,1.4 -0.125,1.4 -0.125,1.05 ; 0.375,-1.4 0.375,-1.05 0.625,-1.05 0.625,-1.4 0.375,-1.4 ; 0.375,1.05 0.625,1.05 0.625,1.4 0.375,1.4 0.375,1.05 ; 1.05,-1.125 1.05,-0.875 1.4,-0.875 1.4,-1.125 1.05,-1.125 ; 1.05,-0.625 1.05,-0.375 1.4,-0.375 1.4,-0.625 1.05,-0.625 ; 1.05,-0.125 1.05,0.125 1.4,0.125 1.4,-0.125 1.05,-0.125 ; 1.05,0.375 1.05,0.625 1.4,0.625 1.4,0.375 1.05,0.375 ; 1.05,0.875 1.05,1.125 1.4,1.125 1.4,0.875 1.05,0.875
  text "13" at 1.385,0.81 h0.5
  text "9" at 1.385,-1.105 h0.5
  text "8" at 0.395,-1.385 h0.5
  text "6" at -0.605,-1.385 h0.5
  text "5" at -1.385,-0.89 h0.5
  text "1" at -1.385,1.07 h0.5
  text "'.Designator'" at -2,-0.5 h0.75
  text "16" at -0.725,1.06 h0.5
  text "14" at 0.29,1.065 h0.5
M16-Top Courtyard:
  lines w0.01: -1.77,-1.77 -1.77,1.77 1.77,1.77 1.77,-1.77 -1.77,-1.77
3D body "User Library-LIS331AL.STEP": height 1.01, standoff -0.01, extent -1.5,-1.5 1.5,1.5
3D body: height 1.1, standoff 0, extent -1.575,-1.575 1.575,1.575

## ICC_LGA16_4X4_P065_H1P1 [mm] "MCD-01963"
height 1.1
pads (16):
  rect 0.85x0.45 smd mask+0.05: 1(-1.8,0.975) 2(-1.8,0.325) 3(-1.8,-0.325) 4(-1.8,-0.975) 9(1.8,-0.975) 10(1.8,-0.325) 11(1.8,0.325) 12(1.8,0.975)
  rect 0.45x0.85 smd mask+0.05: 5(-0.975,-1.8) 6(-0.325,-1.8) 7(0.325,-1.8) 8(0.975,-1.8) 13(0.975,1.8) 14(0.325,1.8) 15(-0.325,1.8) 16(-0.975,1.8)
Top Overlay:
  circle w0.12: c-1.75,1.525 r0.15
  lines w0.12: -2.25,1.375 -2.25,2.25 -1.375,2.25 ; -2.1,-1.325 -2.1,-2.1 -1.325,-2.1 ; -2.1,1.325 -2.1,2.1 -1.325,2.1 ; 1.325,-2.1 2.1,-2.1 2.1,-1.325 ; 1.325,2.1 2.1,2.1 2.1,1.325
M14-Top Assembly:
  circle w0.01: c-1.75,1.525 r0.15
  lines w0.01: -2.1,-2.1 -2.1,2.1 2.1,2.1 2.1,-2.1 -2.1,-2.1 ; -2,-1.125 -1.6,-1.125 -1.6,-0.825 -2,-0.825 -2,-1.125 ; -2,-0.475 -1.6,-0.475 -1.6,-0.175 -2,-0.175 -2,-0.475 ; -2,0.175 -1.6,0.175 -1.6,0.475 -2,0.475 -2,0.175 ; -2,0.825 -1.6,0.825 -1.6,1.125 -2,1.125 -2,0.825 ; -1.125,-2 -0.825,-2 -0.825,-1.6 -1.125,-1.6 -1.125,-2 ; -1.125,1.6 -0.825,1.6 -0.825,2 -1.125,2 -1.125,1.6 ; -0.475,-2 -0.175,-2 -0.175,-1.6 -0.475,-1.6 -0.475,-2 ; -0.475,1.6 -0.175,1.6 -0.175,2 -0.475,2 -0.475,1.6 ; 0.175,-2 0.475,-2 0.475,-1.6 0.175,-1.6 0.175,-2 ; 0.175,1.6 0.475,1.6 0.475,2 0.175,2 0.175,1.6 ; 0.825,-2 1.125,-2 1.125,-1.6 0.825,-1.6 0.825,-2 ; 0.825,1.6 1.125,1.6 1.125,2 0.825,2 0.825,1.6 ; 1.6,-1.125 2,-1.125 2,-0.825 1.6,-0.825 1.6,-1.125 ; 1.6,-0.475 2,-0.475 2,-0.175 1.6,-0.175 1.6,-0.475 ; 1.6,0.175 2,0.175 2,0.475 1.6,0.475 1.6,0.175 ; 1.6,0.825 2,0.825 2,1.125 1.6,1.125 1.6,0.825
  text "'.Designator'" at -2,-0.5 h0.75
  text "1" at -1.975,1.025 h0.5
  text "4" at -1.975,-0.875 h0.5
  text "5" at -1.075,-1.975 h0.5
  text "8" at 0.875,-1.975 h0.5
  text "9" at 1.975,-1.075 h0.5
  text "12" at 1.975,0.75 h0.5
  text "13" at 0.75,1.65 h0.5
  text "16" at -1.2,1.65 h0.5
M16-Top Courtyard:
  lines w0.01: -2.375,-2.375 2.375,-2.375 2.375,2.375 -2.375,2.375 -2.375,-2.375
3D body "LGA-16.STEP": height 0.98, standoff 0, extent -2,-2 2,2
3D body: height 1.1, standoff 0, extent -2.1,-2.1 2.1,2.1

## ICC_LGA16_6P4X3_P075_H1P5 [mm] "MCD-02257"
height 1.5
pads (17):
  rect 0.5x0.5 smd mask+0.05: A1(2.25,-1.05) A2(1.5,-1.05) A3(0.75,-1.05) A4(0,-1.05) A5(-0.75,-1.05) A6(-1.5,-1.05) A7(-2.25,-1.05) B1(2.65,0) B7(-2.65,0) C1(2.25,1.05) C2(1.5,1.05) C3(0.75,1.05) C4(0,1.05) C5(-0.75,1.05) C6(-1.5,1.05) C7(-2.25,1.05)
  rect 2.316x1.2 smd mask+0.05: B4(0,0)
Top Overlay:
  lines w0.12: -3.1,-1.5 3.1,-1.5 3.1,1.5 -3.1,1.5 -3.1,-1.5
  text "A1" at 1.975,-2.35 h1.2
M14-Top Assembly:
  lines w0.01: -3.1,-1.5 -3.1,1.5 3.1,1.5 3.1,-1.5 -3.1,-1.5 ; -2.9,-0.25 -2.9,0.25 -2.4,0.25 -2.4,-0.25 -2.9,-0.25 ; -2.5,-1.3 -2.5,-0.8 -2,-0.8 -2,-1.3 -2.5,-1.3 ; -2.5,0.8 -2.5,1.3 -2,1.3 -2,0.8 -2.5,0.8 ; -1.75,-1.3 -1.75,-0.8 -1.25,-0.8 -1.25,-1.3 -1.75,-1.3 ; -1.75,0.8 -1.75,1.3 -1.25,1.3 -1.25,0.8 -1.75,0.8 ; -1.158,-0.6 -1.158,0.6 1.158,0.6 1.158,-0.6 -1.158,-0.6 ; -1,-1.3 -1,-0.8 -0.5,-0.8 -0.5,-1.3 -1,-1.3 ; -1,0.8 -1,1.3 -0.5,1.3 -0.5,0.8 -1,0.8 ; -0.25,-1.3 -0.25,-0.8 0.25,-0.8 0.25,-1.3 -0.25,-1.3 ; -0.25,0.8 -0.25,1.3 0.25,1.3 0.25,0.8 -0.25,0.8 ; 0.5,-1.3 0.5,-0.8 1,-0.8 1,-1.3 0.5,-1.3 ; 0.5,0.8 0.5,1.3 1,1.3 1,0.8 0.5,0.8 ; 1.25,-1.3 1.25,-0.8 1.75,-0.8 1.75,-1.3 1.25,-1.3 ; 1.25,0.8 1.25,1.3 1.75,1.3 1.75,0.8 1.25,0.8 ; 2,-1.3 2.5,-1.3 2.5,-0.8 2,-0.8 2,-1.3 ; 2,0.8 2,1.3 2.5,1.3 2.5,0.8 2,0.8 ; 2.4,-0.25 2.4,0.25 2.9,0.25 2.9,-0.25 2.4,-0.25
  text "B4" at -0.25,-0.15 h0.5
  text "B7" at -2.9,-0.15 h0.5
  text "B1" at 2.425,-0.15 h0.5
  text "C7" at -2.5,0.9 h0.5
  text "C1" at 2,0.9 h0.5
  text "A7" at -2.5,-1.2 h0.5
  text "A1" at 2,-1.2 h0.5
  text "'.Designator'" at -2,-0.5 h0.75
M16-Top Courtyard:
  lines w0.01: -3.3,-1.625 3.3,-1.625 3.3,1.7 -3.3,1.7 -3.3,-1.625
3D body: height 1.51, standoff 1.5, extent -2.038,-0.354 -1.53,0.155
3D body: height 1.51, standoff 1.5, extent 1.855,-0.5 2.575,0.3
3D body: height 1.5, standoff 0, extent -3.1,-1.5 3.1,1.5

## ICC_LGA105_11X12_P070_H1P6 [mm] "MCD-04288"
height 1.6
pads (105):
  rect 0.55x0.35 smd mask+0.04: 1(-5.5,3.5) 2(-5.5,2.8) 3(-5.5,2.1) 4(-5.5,1.4) 5(-5.5,0.7) 6(-5.5,0) 7(-5.5,-0.7) 8(-5.5,-1.4) 9(-5.5,-2.1) 10(-5.5,-2.8) 11(-5.5,-3.5) 27(5.5,-3.5) 28(5.5,-2.8) 29(5.5,-2.1) 30(5.5,-1.4) 31(5.5,-0.7) 32(5.5,0) 33(5.5,0.7) 34(5.5,1.4) 35(5.5,2.1) 36(5.5,2.8) 37(5.5,3.5)
  rect 0.35x0.55 smd mask+0.04: 12(-4.9,-5) 13(-4.2,-5) 14(-3.5,-5) 15(-2.8,-5) 16(-2.1,-5) 17(-1.4,-5) 18(-0.7,-5) 19(0,-5) 20(0.7,-5) 21(1.4,-5) 22(2.1,-5) 23(2.8,-5) 24(3.5,-5) 25(4.2,-5) 26(4.9,-5) 38(4.9,5) 39(4.2,5) 40(3.5,5) 41(2.8,5) 42(2.1,5) 43(1.4,5) 44(0.7,5) 45(0,5) 46(-0.7,5) 47(-1.4,5) 48(-2.1,5) 49(-2.8,5) 50(-3.5,5) 51(-4.2,5) 52(-4.9,5)
  rect 0.65x0.65 smd mask+0.04: 53(-4,3) 54(-4,-3) 55(-3,-3) 56(-2,-3) 57(-1,-3) 58(0,-3) 59(1,-3) 60(2,-3) 61(3,-3) 62(4,-3) 63(4,3) 64(3,3) 65(2,3) 66(1,3) 67(0,3) 68(-1,3) 69(-2,3) 70(-3,3) 71(-3,2) 72(-3,1) 73(-3,0) 74(-3,-1) 75(-3,-2) 76(-2,-2) 77(-1,-2) 78(0,-2) 79(1,-2) 80(2,-2) 81(3,-2) 82(3,-1) 83(3,0) 84(3,1) 85(3,2) 86(2,2) 87(1,2) 88(0,2) 89(-1,2) 90(-2,2) 91(-2,1) 92(-2,0) 93(-2,-1) 94(-1,-1) 95(0,-1) 96(1,-1) 97(2,-1) 98(2,0) 99(2,1) 100(1,1) 101(0,1) 102(-1,1) 103(-1,0) 104(0,0) 105(1,0)
Top Overlay:
  lines w0.12: -6,-5.5 6,-5.5 6,5.5 -6,5.5 -6,-5.5
  text "1" at -6.475,3.05 h1.5
Bottom 3D Body:
  circle w0.005: c0.973,-3.305 r0.002
  circle w0.005: c-0.927,-3.305 r0.002
  circle w0.005: c3.628,5.125 r0.002
  circle w0.005: c-3.582,-5.9 r0.002
  circle w0.005: c-3.582,-6.45 r0.002
  circle w0.005: c-2.977,-6.53 r0.002
  circle w0.005: c-3.502,-6.53 r0.002
  circle w0.005: c1.053,-1.125 r0.002
  circle w0.005: c1.053,-3.225 r0.002
  circle w0.005: c3.628,5.125 r0.002
  circle w0.005: c4.023,-6.925 r0.002
  circle w0.005: c-3.977,-6.925 r0.002
  circle w0.005: c4.023,-6.925 r0.002
  circle w0.005: c3.628,5.125 r0.002
  circle w0.005: c3.628,-6.45 r0.002
  circle w0.005: c-0.977,-6.53 r0.002
  circle w0.005: c-0.477,-6.53 r0.002
  circle w0.005: c3.628,-2.225 r0.002
  circle w0.005: c3.628,-2.75 r0.002
  circle w0.005: c-3.502,5.205 r0.002
  circle w0.005: c3.548,5.205 r0.002
  circle w0.005: c-1.007,-1.125 r0.002
  circle w0.005: c-0.927,-1.045 r0.002
  circle w0.005: c-3.502,-6.53 r0.002
  circle w0.005: c3.548,-6.53 r0.002
  circle w0.005: c3.548,5.205 r0.002
  circle w0.005: c2.923,5.205 r0.002
  circle w0.005: c2.843,4.5 r0.002
  circle w0.005: c2.843,5.125 r0.002
M14-Top Assembly:
  drawing of 425 lines, arcs and shapes, not listed
  text ".'Designator'" at -2,-0.134 h0.75
  text "1" at -5.65,3.225 h1
  text "11" at -5.9,-3.775 h1
  text "12" at -5.375,-5.3 h1
  text "26" at 4.499,-5.289 h1
  text "27" at 4.999,-3.8 h1
  text "37" at 5,3.236 h1
  text "38" at 4.45,4.675 h1
  text "52" at -5.425,4.675 h1
  text "53" at -4.425,2.675 h1
  text "54" at -4.45,-3.325 h1
  text "62" at 3.575,-3.325 h1
  text "63" at 3.575,2.675 h1
  text "71" at -3.475,1.664 h1
  text "75" at -3.425,-2.3 h1
  text "81" at 2.525,-2.325 h1
  text "85" at 2.525,1.675 h1
  text "91" at -2.475,0.675 h1
  text "93" at -2.475,-1.325 h1
  text "97" at 1.525,-1.325 h1
  text "99" at 1.525,0.675 h1
  text "103" at -1.725,-0.339 h1
  text "105" at 0.325,-0.314 h1
M16-Top Courtyard:
  lines w0.01: -6.25,-5.75 -6.25,5.75 6.25,5.75 6.25,-5.75 -6.25,-5.75
3D body: height 1.6, standoff 0, extent -6,-5.5 6,5.5
3D body: height 1.61, standoff 0.05, extent -5.795,4.88 -5.355,5.32

## ICC_LGA107_8X14_P050_H1P6 [mm] "MCD-04154"
height 1.6
pads (107):
  rect 0.35x0.3 smd mask+0.04: 1(-3.525,6.525) 2(-3.525,6.025) 3(-3.525,5.525) 4(-3.525,5.025) 5(-3.525,4.525) 6(-3.525,4.025) 8(-3.525,2.975) 9(-3.525,2.475) 10(-3.525,1.975) 11(-3.525,1.475) 12(-3.525,0.975) 13(-3.525,0.475) 14(-3.525,-0.025) 15(-3.525,-0.525) 16(-3.525,-1.025) 17(-3.525,-1.525) 18(-3.525,-2.025) 19(-3.525,-2.525) 20(-3.525,-3.025) 21(-3.525,-3.525) 22(-3.525,-4.025) 23(-3.525,-4.525) 24(-3.525,-5.025) 25(-3.525,-5.525) 26(-3.525,-6.025) 27(-3.525,-6.525) 41(3.525,-6.525) 42(3.525,-6.025) 43(3.525,-5.525) 44(3.525,-5.025) 45(3.525,-4.525) 46(3.525,-4.025) 47(3.525,-3.525) 48(3.525,-3.025) 49(3.525,-2.525) 50(3.525,-2.025) 51(3.525,-1.525) 53(3.525,-0.525) 54(3.525,-0.025) 55(3.525,0.475) 56(3.525,0.975) 57(3.525,1.475) 58(3.525,1.975) 59(3.525,2.475) 60(3.525,2.975) 62(3.525,4.025) 63(3.525,4.525) 64(3.525,5.025) 65(3.525,5.525) 66(3.525,6.025) 67(3.525,6.525)
  rect 0.35x0.35 smd mask+0.04: 7(-3.525,3.5) 52(3.525,-1.025) 61(3.525,3.5)
  rect 0.3x0.35 smd mask+0.04: 28(-3,-6.5) 29(-2.5,-6.5) 30(-2,-6.5) 31(-1.5,-6.5) 32(-1,-6.5) 33(-0.5,-6.5) 34(0,-6.5) 35(0.5,-6.5) 36(1,-6.5) 37(1.5,-6.5) 38(2,-6.5) 39(2.5,-6.5) 40(3,-6.5) 74(3,3.5) 75(2.5,3.5) 76(2,3.5) 77(1.5,3.5) 78(1,3.5) 79(0.5,3.5) 80(0,3.5) 81(-0.5,3.5) 82(-1,3.5) 83(-1.5,3.5) 84(-2,3.5) 85(-2.5,3.5) 86(-3,3.5)
  rect 0.3x0.3 smd mask+0.04: 68(3,6.525) 69(3,6.025) 70(3,5.525) 71(3,5.025) 72(3,4.525) 73(3,4.025)
  rect 0.4x0.4 smd mask+0.04: 87(1.723,2.819) 88(1.723,0.983) 89(2.897,0.321) 90(-1.2,-1.325) 91(-1.2,-2.125) 92(-1.2,-2.925) 93(-1.2,-3.725) 94(-1.2,-4.525) 95(-0.4,-4.525) 96(0.4,-4.525) 97(1.2,-4.525) 98(1.2,-3.725) 99(1.2,-2.925) 100(0.4,-1.325) 101(-0.4,-1.325) 102(-0.4,-2.125) 103(-0.4,-2.925) 104(-0.4,-3.725) 105(0.4,-3.725) 106(0.4,-2.925) 107(-2.216,-5.356)
Top Overlay:
  lines w0.12: -4,-7 -4,7 4,7 4,-7 -4,-7
  text "1" at -4.475,6.125 h1.5
Bottom 3D Body:
  circle w0.005: c2.843,5.125 r0.002
  circle w0.005: c2.843,4.5 r0.002
  circle w0.005: c2.923,5.205 r0.002
  circle w0.005: c3.548,5.205 r0.002
  circle w0.005: c3.548,-6.53 r0.002
  circle w0.005: c-3.502,-6.53 r0.002
  circle w0.005: c-0.927,-1.045 r0.002
  circle w0.005: c-1.007,-1.125 r0.002
  circle w0.005: c3.548,5.205 r0.002
  circle w0.005: c-3.502,5.205 r0.002
  circle w0.005: c3.628,-2.75 r0.002
  circle w0.005: c3.628,-2.225 r0.002
  circle w0.005: c-0.477,-6.53 r0.002
  circle w0.005: c-0.977,-6.53 r0.002
  circle w0.005: c3.628,-6.45 r0.002
  circle w0.005: c3.628,5.125 r0.002
  circle w0.005: c4.023,-6.925 r0.002
  circle w0.005: c-3.977,-6.925 r0.002
  circle w0.005: c4.023,-6.925 r0.002
  circle w0.005: c3.628,5.125 r0.002
  circle w0.005: c1.053,-3.225 r0.002
  circle w0.005: c1.053,-1.125 r0.002
  circle w0.005: c-3.502,-6.53 r0.002
  circle w0.005: c-2.977,-6.53 r0.002
  circle w0.005: c-3.582,-6.45 r0.002
  circle w0.005: c-3.582,-5.9 r0.002
  circle w0.005: c3.628,5.125 r0.002
  circle w0.005: c-0.927,-3.305 r0.002
  circle w0.005: c0.973,-3.305 r0.002
M14-Top Assembly:
  drawing of 435 lines, arcs and shapes, not listed
  text ".'Designator'" at -2,-0.359 h0.75
M16-Top Courtyard:
  lines w0.01: -4.25,-7.25 4.25,-7.25 4.25,7.25 -4.25,7.25 -4.25,-7.25
3D body: height 1.61, standoff 0.05, extent -3.72,6.472 -3.28,6.912
3D body: height 1.6, standoff 0, extent -4,3.825 4,7
3D body: height 1.6, standoff 0, extent -4,-7 4,3.825

## ICC_LQFP32_7X7_P080 [mm] "MCD-01339"
height 1.6
pads (32):
  rect 0.5x1.2 smd mask+0.05: 1(-2.8,-4.25) 2(-2,-4.25) 3(-1.2,-4.25) 4(-0.4,-4.25) 5(0.4,-4.25) 6(1.2,-4.25) 7(2,-4.25) 8(2.8,-4.25) 17(2.8,4.25) 18(2,4.25) 19(1.2,4.25) 20(0.4,4.25) 21(-0.4,4.25) 22(-1.2,4.25) 23(-2,4.25) 24(-2.8,4.25)
  rect 1.2x0.5 smd mask+0.05: 9(4.25,-2.8) 10(4.25,-2) 11(4.25,-1.2) 12(4.25,-0.4) 13(4.25,0.4) 14(4.25,1.2) 15(4.25,2) 16(4.25,2.8) 25(-4.25,2.8) 26(-4.25,2) 27(-4.25,1.2) 28(-4.25,0.4) 29(-4.25,-0.4) 30(-4.25,-1.2) 31(-4.25,-2) 32(-4.25,-2.8)
Top Overlay:
  circle w0.12: c-2.9,-2.925 r0.326
  lines w0.12: -3.525,-3.25 -3.25,-3.525 -2.775,-3.525 3.25,-3.525 3.525,-3.25 3.525,-2.8 3.525,3.25 3.25,3.525 2.85,3.525 -2.95,3.525 -3.275,3.525 -3.525,3.275 -3.525,3 -3.525,-3.25
  text "1" at -3.525,-4.625 h1.5
M14-Top Assembly:
  circle w0.01: c-2.9,-2.925 r0.335
  lines w0.01: -3.6,-3 -4.6,-3 -4.6,-2.6 -3.6,-2.6 ; -3.6,-2.2 -4.6,-2.2 -4.6,-1.8 -3.6,-1.8 ; -3.6,-1.4 -4.6,-1.4 -4.6,-1 -3.6,-1 ; -3.6,-0.6 -4.6,-0.6 -4.6,-0.2 -3.6,-0.2 ; -3.6,0.2 -4.6,0.2 -4.6,0.6 -3.6,0.6 ; -3.6,1 -4.6,1 -4.6,1.4 -3.6,1.4 ; -3.6,1.8 -4.6,1.8 -4.6,2.2 -3.6,2.2 ; -3.6,2.6 -4.6,2.6 -4.6,3 -3.6,3 ; -3,-3.6 -3,-4.6 -2.6,-4.6 -2.6,-3.6 ; -3,3.6 -3,4.6 -2.6,4.6 -2.6,3.6 ; -2.2,-3.6 -2.2,-4.6 -1.8,-4.6 -1.8,-3.6 ; -2.2,3.6 -2.2,4.6 -1.8,4.6 -1.8,3.6 ; -1.4,-3.6 -1.4,-4.6 -1,-4.6 -1,-3.6 ; -1.4,3.6 -1.4,4.6 -1,4.6 -1,3.6 ; -0.6,-3.6 -0.6,-4.6 -0.2,-4.6 -0.2,-3.6 ; -0.6,3.6 -0.6,4.6 -0.2,4.6 -0.2,3.6 ; 0.2,-3.6 0.2,-4.6 0.6,-4.6 0.6,-3.6 ; 0.2,3.6 0.2,4.6 0.6,4.6 0.6,3.6 ; 1,-3.6 1,-4.6 1.4,-4.6 1.4,-3.6 ; 1,3.6 1,4.6 1.4,4.6 1.4,3.6 ; 1.8,-3.6 1.8,-4.6 2.2,-4.6 2.2,-3.6 ; 1.8,3.6 1.8,4.6 2.2,4.6 2.2,3.6 ; 2.6,-3.6 2.6,-4.6 3,-4.6 3,-3.6 ; 2.6,3.6 2.6,4.6 3,4.6 3,3.6 ; 3.6,-3 4.6,-3 4.6,-2.6 3.6,-2.6 ; 3.6,-2.2 4.6,-2.2 4.6,-1.8 3.6,-1.8 ; 3.6,-1.4 4.6,-1.4 4.6,-1 3.6,-1 ; 3.6,-0.6 4.6,-0.6 4.6,-0.2 3.6,-0.2 ; 3.6,0.2 4.6,0.2 4.6,0.6 3.6,0.6 ; 3.6,1 4.6,1 4.6,1.4 3.6,1.4 ; 3.6,1.8 4.6,1.8 4.6,2.2 3.6,2.2 ; 3.6,2.6 4.6,2.6 4.6,3 3.6,3 ; -3.6,-3.3 -3.3,-3.6 3.3,-3.6 3.6,-3.3 3.6,3.3 3.3,3.6 -3.3,3.6 -3.6,3.3 -3.6,-3.3 ; -3.5,-3.25 -3.25,-3.5 3.25,-3.5 3.5,-3.25 3.5,3.25 3.25,3.5 -3.25,3.5 -3.5,3.25 -3.5,-3.25
  text "'.Designator'" at -2,-0.5 h0.75
  text "1" at -3.425,-4.625 h1.5
M16-Top Courtyard:
  lines w0.025: -5,-5 -5,5 5,5 5,-5 -5,-5
3D body: height 1.6, standoff 0, extent -3.585,-3.585 3.585,3.585
3D body "LQFP32_7x7_p080.STEP": height 1.63, standoff -0.09, extent -4.5,-4.5 4.5,4.5

## ICC_LQFP32_7X7_P080__UFQFPN32-EPAD_5X5_P050__DI [mm] "MCD-01396"
height 1.6
pads (65):
  rect 0.5x1.2 smd mask+0.05: 1(-2.8,-4.25) 2(-2,-4.25) 3(-1.2,-4.25) 4(-0.4,-4.25) 5(0.4,-4.25) 6(1.2,-4.25) 7(2,-4.25) 8(2.8,-4.25) 17(2.8,4.25) 18(2,4.25) 19(1.2,4.25) 20(0.4,4.25) 21(-0.4,4.25) 22(-1.2,4.25) 23(-2,4.25) 24(-2.8,4.25)
  oval 0.3x0.75 smd mask+0.05: 1(-1.75,-2.425) 2(-1.25,-2.425) 3(-0.75,-2.425) 4(-0.25,-2.425) 5(0.25,-2.425) 6(0.75,-2.425) 7(1.25,-2.425) 8(1.75,-2.425) 17(1.75,2.425) 18(1.25,2.425) 19(0.75,2.425) 20(0.25,2.425) 21(-0.25,2.425) 22(-0.75,2.425) 23(-1.25,2.425) 24(-1.75,2.425)
  oval 0.75x0.3 smd mask+0.05: 9(2.425,-1.75) 10(2.425,-1.25) 11(2.425,-0.75) 12(2.425,-0.25) 13(2.425,0.25) 14(2.425,0.75) 15(2.425,1.25) 16(2.425,1.75) 25(-2.425,1.75) 26(-2.425,1.25) 27(-2.425,0.75) 28(-2.425,0.25) 29(-2.425,-0.25) 30(-2.425,-0.75) 31(-2.425,-1.25) 32(-2.425,-1.75)
  rect 1.2x0.5 smd mask+0.05: 9(4.25,-2.8) 10(4.25,-2) 11(4.25,-1.2) 12(4.25,-0.4) 13(4.25,0.4) 14(4.25,1.2) 15(4.25,2) 16(4.25,2.8) 25(-4.25,2.8) 26(-4.25,2) 27(-4.25,1.2) 28(-4.25,0.4) 29(-4.25,-0.4) 30(-4.25,-1.2) 31(-4.25,-2) 32(-4.25,-2.8)
  rect 3.7x3.7 smd mask+0.05: 33(0,0)
Top Overlay:
  circle w0.12: c-2.3,-2.3 r0.2
  circle w0.12: c-3.1,-3.125 r0.225
  lines w0.12: -2.625,-2.05 -2.625,-2.625 -2.05,-2.625 ; -2.625,2.05 -2.625,2.625 -2.05,2.625 ; 2.05,-2.625 2.625,-2.625 2.625,-2.05 ; 2.05,2.625 2.625,2.625 2.625,2.05 ; -3.525,-3.25 -3.25,-3.525 -2.775,-3.525 3.25,-3.525 3.525,-3.25 3.525,-2.8 3.525,3.25 3.25,3.525 2.85,3.525 -2.95,3.525 -3.275,3.525 -3.525,3.275 -3.525,3 -3.525,-3.25
  text "1" at -2,-3.075 h1.5
  text "1" at -3.525,-4.625 h1.5
M14-Top Assembly:
  drawing of 218 lines, arcs and shapes, not listed
  text "33" at -0.275,-0.15 h0.5
  text "32" at -2.45,-1.525 h0.5
  text "25" at -2.45,2 h0.5
  text "24" at -1.975,2.175 h0.5
  text "17" at 1.55,2.15 h0.5
  text "16" at 2.45,1.575 h0.5
  text "9" at 2.45,-1.85 h0.5
  text "8" at 1.65,-2.475 h0.5
  text "1" at -1.8,-2.475 h0.5
  text "'.Designator'" at -2,0.25 h0.75
  text "1" at -3,-4.65 h1.5
  text "8" at 2.475,-4.625 h1.5
  text "9" at 4.675,-3.125 h1.5
  text "16" at 4.625,2.225 h1.5
  text "17" at 2.175,3.7 h1.5
  text "24" at -3.5,3.7 h1.5
  text "25" at -4.65,3.525 h1.5
  text "32" at -4.65,-2.15 h1.5
M16-Top Courtyard:
  lines w0.01: -5,-5 -5,5 5,5 5,-5 -5,-5
3D body "UFQFPN-32.STEP": height 0.55, standoff 0, extent -2.5,-2.5 2.5,2.5
3D body: height 1.6, standoff 0, extent -3.585,-3.585 3.585,3.585
3D body "LQFP32_7x7_p080.STEP": height 1.63, standoff -0.09, extent -4.5,-4.5 4.5,4.5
